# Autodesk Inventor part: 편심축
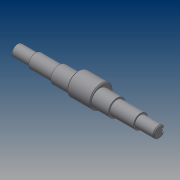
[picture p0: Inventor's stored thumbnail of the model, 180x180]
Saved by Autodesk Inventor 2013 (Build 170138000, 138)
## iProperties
Created: 2014-12
Part Number: 편심축
Material: Generic
Document SubType Name: Modeling
Designer: SD
Density: 1 g/cm^3
Author: SD
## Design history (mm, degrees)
sketch "스케치1"
  geometry: L1 (-75.5, 0)-(75.5, 0); L2 (-75.5, 0)-(-75.5, 6); L3 (-75.5, 6)-(-55.5, 6); L4 (-55.5, 6)-(-55.5, 7.5); L5 (-55.5, 7.5)-(-30.5, 7.5); L6 (-30.5, 7.5)-(-30.5, 9); L7 (-30.5, 9)-(30.5, 9); L8 (30.5, 9)-(30.5, 7.5); L9 (30.5, 7.5)-(55.5, 7.5); L10 (55.5, 7.5)-(55.5, 6); L11 (55.5, 6)-(75.5, 6); L12 (75.5, 6)-(75.5, 0); L13 (-75.5, 6)-(-61.5, 6); L14 (-61.5, 6)-(-61.5, 3); L15 (-61.5, 3)-(-75.5, 3); L16 (-75.5, 3)-(-75.5, 6); L17 (61.5, 6)-(75.5, 6); L18 (75.5, 6)-(75.5, 3); L19 (75.5, 3)-(61.5, 3); L20 (61.5, 3)-(61.5, 6); L21 (-12.5, 14)-(12.5, 14); L22 (12.5, 14)-(12.5, 2); L23 (12.5, 2)-(-12.5, 2); L24 (-12.5, 2)-(-12.5, 14); 2 further points
  constraints: 48 end point, 14 parallel, 5 perpendicular, 4 horizontal, 2 midpoint, 1 coincident, 1 collinear, 1 point on line
  dimensions: "d0" = 151 distance of L1.start L1.end; "d2" = 12 diameter of L3 L1; "d3" = 15 diameter of L5 L1; "d4" = 18 diameter of L7 L1; "d5" = 12 diameter of L11 L1; "d6" = 15 diameter of L9 L1; "d7" = 20 distance of L2.end L3.end; "d8" = 25 distance of L4.end L5.end; "d9" = 20 distance of L10.end L11.end; "d10" = 25 distance of L8.end L9.end; "d11" = 3 distance of L13.end L14.end; "d12" = 14 distance of L14.end L15.end; "d13" = 3 distance of L19.end L17.start; "d14" = 14 distance of L18.end L19.end; "d15" = 18 distance between parallel lines of L24 L6; "d16" = 2 distance from line of point (0, 0) L23; "d17" = 12 distance between parallel lines of L21 L23; "d18" = 18 distance between parallel lines of L8 L22
revolve "회전1" stored, may be unused: angle "d19" = 90 deg
revolve "회전2" stored, may be unused: angle "d20" = 90 deg
extrude "돌출1" cut sketch "스케치1" stored distance "d21" = 5; taper "d22" = 0 deg
fillet "모깎기1" dims "d23" = 2.5
chamfer "모따기1" distance "d24" = 1; stored, may be unused: second distance "d25" = 2, angle "d26" = 45 deg
node "솔리드1"
